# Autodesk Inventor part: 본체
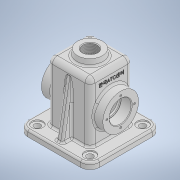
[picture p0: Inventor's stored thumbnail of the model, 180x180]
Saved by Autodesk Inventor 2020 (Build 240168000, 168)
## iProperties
Created: 2021-07
Part Number: 본체
Material: 일반
Document SubType Name: Modeling
Designer: Owner
Density: 1 g/cm^3
Appearance: 기본값
Author: Owner
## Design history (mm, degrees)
sketch "스케치1"
  geometry: L1 (34, 34)-(-34, 34); L2 (-34, 34)-(-34, -34); L3 (-34, -34)-(34, -34); L4 (34, -34)-(34, 34); L5 (34, 34)-(-34, -34); L6 (-34, 34)-(34, -34); 1 further point
  constraints: 12 end point, 2 midpoint, 2 parallel, 1 horizontal, 1 perpendicular
  dimensions: "d0" = 68 distance of L3.end L2.end; "d1" = 68 distance of L2.end L1.end
extrude "돌출1" new body sketch "스케치1" distance "d2" = 52; taper "d3" = 0 deg
extrude "돌출2" join sketch "스케치1" distance "d4" = 53; taper "d5" = 0 deg
sketch "스케치2"
  geometry: L1 (-29, 29)-(29, 29); L2 (29, 29)-(29, -29); L3 (29, -29)-(-29, -29); L4 (-29, -29)-(-29, 29); L5 (-29, 29)-(29, -29); L6 (29, 29)-(-29, -29); 1 further point
  constraints: 12 end point, 2 midpoint, 2 parallel, 1 horizontal, 1 perpendicular
  dimensions: "d6" = 58 distance of L1.end L2.end; "d7" = 58 distance of L2.end L3.end
extrude "돌출3" cut sketch "스케치2" distance "d8" = 100; taper "d9" = 0 deg
sketch "스케치9"
  geometry: C1 r 28.5 at (34, 52); 1 further point
  constraints: 1 centre point, 1 coincident
  dimensions: "d30" = 57 diameter of C1
extrude "돌출10" join sketch "스케치9" distance "d31" = 15; taper "d32" = 0 deg
sketch "스케치10"
  geometry: C1 r 17.5 at (0, 0); 1 further point
  constraints: 1 centre point, 1 coincident
  dimensions: "d33" = 35 diameter of C1
extrude "돌출11" cut sketch "스케치10" distance "d34" = 17; taper "d35" = 0 deg
sketch "스케치11"
  geometry: C1 r 15 at (0, 0); 1 further point
  constraints: 1 centre point, 1 coincident
  dimensions: "d36" = 30 diameter of C1
extrude "돌출12" cut sketch "스케치11" extent not by distance; stored distance "d37" = 17; taper "d38" = 0 deg
sketch "스케치12"
  geometry: 2 further points
  constraints: 1 vertical alignment
  dimensions: "d39" = 22 distance of point (0, 0) point (0, 22)
hole "구멍1" sketch "스케치12" at (0, 22) diameter "d40" = 3.242; stored, may be unused: countersink angle "d44" = 90 deg, drill point angle "d46" = 118 deg; dims "d41" = 8, "d42" = 4, "d43" = 2, "d45" = 10
sketch "스케치13"
  geometry: L1 (-57, 57)-(57, 57); L2 (57, 57)-(57, -57); L3 (57, -57)-(-57, -57); L4 (-57, -57)-(-57, 57); L5 (-57, 57)-(57, -57); L6 (57, 57)-(-57, -57); L7 (-29, 29)-(29, 29) reference; L8 (-29, -29)-(-29, 29) reference; L9 (29, -29)-(-29, -29) reference; L10 (29, 29)-(29, -29) reference; 1 further point
  constraints: 12 end point, 2 midpoint, 2 parallel, 1 horizontal, 1 perpendicular
  dimensions: "d50" = 114 distance of L2.end L3.end; "d51" = 114 distance of L1.end L2.end
extrude "돌출13" join sketch "스케치13" distance "d52" = 10; taper "d53" = 0 deg
fillet "모깎기3" dims "d54" = 15
fillet "모깎기4" dims "d55" = 8
fillet "모깎기5" dims "d56" = 3
sketch "스케치14"
  geometry: L1 (-57, 42)-(-57, -42) reference; L2 (-42, -57)-(42, -57) reference; L3 (57, -42)-(57, 42) reference; L4 (42, 57)-(-42, 57) reference; L5 (-26, -34)-(26, -34) reference; L6 (-34, 26)-(-34, -26) reference; L7 (26, 34)-(-26, 34) reference; L8 (34, -26)-(34, 26) reference; A1 r 15 centre (-42, 42) between (-42, 57) and (-57, 42) reference; A2 r 15 centre (-42, -42) between (-57, -42) and (-42, -57) reference; A3 r 15 centre (42, -42) between (42, -57) and (57, -42) reference; A4 r 15 centre (42, 42) between (57, 42) and (42, 57) reference; A5 r 8 centre (26, -26) between (26, -34) and (34, -26) reference; A6 r 8 centre (-26, -26) between (-34, -26) and (-26, -34) reference; A7 r 8 centre (-26, 26) between (-26, 34) and (-34, 26) reference; A8 r 8 centre (26, 26) between (34, 26) and (26, 34) reference; 1 further point
hole "구멍2" sketch "스케치14" at (-42, -42), (42, -42), (42, 42), (-42, 42) diameter "d57" = 10; stored, may be unused: countersink angle "d61" = 90 deg, drill point angle "d63" = 118 deg; dims "d58" = 8, "d59" = 18, "d60" = 2, "d62" = 20
sketch "스케치15"
  geometry: L1 (-44, 33)-(-44, 51) reference; L2 (-42, 49)-(43.069, 34); L3 (-42, 34)-(45, 34) reference; L4 (-42, 51)-(-42, 33) reference; L5 (-52, 57)-(-42, 57) reference; 1 further point
  constraints: 2 end point, 2 point on line
  dimensions: "d64" = 8 distance from line of L5 L2.start; "d65" = 10 deg angle of L2 L3
extrude "돌출14" join sketch "스케치15" stored distance "d66" = 10; taper "d67" = 0 deg
node "작업 평면3"
sketch "스케치16"
  geometry: C1 r 20 at (0, 0); 1 further point
  constraints: 1 centre point, 1 coincident
  dimensions: "d69" = 40 diameter of C1
extrude "돌출15" join sketch "스케치16" distance "d70" = 10; taper "d71" = 8 deg
sketch "스케치17"
  geometry: C1 r 20 at (0, 0) reference; 1 further point
hole "구멍3" sketch "스케치17" at (0, 0) diameter "d72" = 22.83494; stored, may be unused: countersink angle "d76" = 90 deg, drill point angle "d78" = 118 deg; dims "d73" = 50, "d74" = 18, "d75" = 2, "d77" = 59.3
fillet "모깎기6" dims "d79" = 3
fillet "모깎기7" dims "d80" = 3
fillet "모깎기8" dims "d81" = 3
fillet "모깎기9" dims "d82" = 3
fillet "모깎기10" dims "d83" = 3
fillet "모깎기11" dims "d84" = 3
chamfer "모따기1" distance "d85" = 1; stored, may be unused: second distance "d86" = 2, angle "d87" = 45 deg
fillet "모깎기12" dims "d88" = 0.3
fillet "모깎기13" dims "d89" = 3
fillet "모깎기14" dims "d90" = 3
sketch "스케치18"
  geometry: L1 (6, 18)-(46, 18) reference; 2 further points
  constraints: 1 vertical alignment, 1 other
  dimensions: "d91" = 25 distance from line of L1 point (26, -7)
feature "엠보싱1" sketch "스케치18" dims "d92" = 0.5, "d93" = 0
fillet "모깎기15" dims "d94" = 3
node "솔리드1"
pattern_circular "원형 패턴1" dims angle "d48" = 360 deg
mirror "미러2"
mirror "미러3"
node "투영된 루프1"
node "투영된 루프2"
node "투영된 루프3"
feature "A9D066F2-1C7D-4E18-AEED-F7BC21143FA4" dims "d57" = 10, "d58" = 8, "d59" = 18, "d60" = 2, "d61" = 90 deg, "d62" = 20, "d63" = 118 deg
other parameters: "d68" = -115
